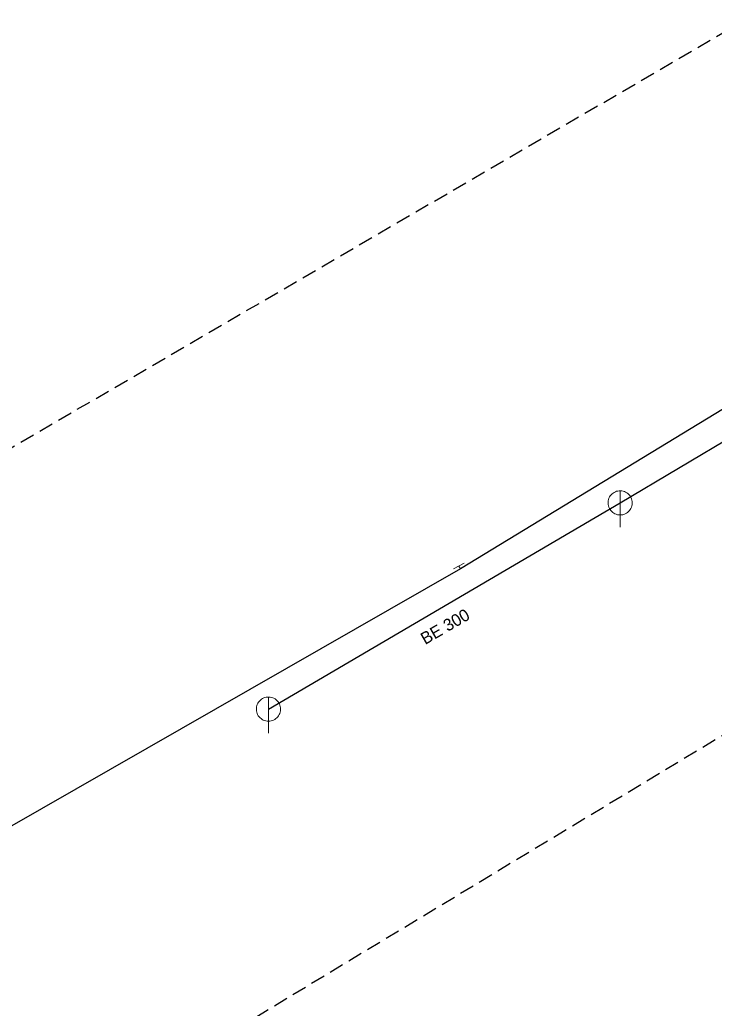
# Model space of a CAD drawing. Extents: x -689189 to -688666, y -973229 to -972850.
# Drawn here: x -689130.1 to -689072.6, y -973144.4 to -973062.7 of the extents above; entities that cross this region are included whole.
import ezdxf

# ---------------------------------------------------------------- set-up
doc = ezdxf.new("R2010")
doc.units = 0
doc.header["$LTSCALE"] = 0.4
doc.linetypes.add('MEDIUM_DASHED', pattern=[4.5, 3, -1.5])
doc.layers.add('1', color=7, linetype='Continuous')
for name, color, linetype, lineweight in [('14', 7, 'Continuous', 13), ('17', 7, 'Continuous', 25), ('22', 7, 'Continuous', 13), ('34', 7, 'Continuous', 13), ('63', 7, 'MEDIUM_DASHED', 25)]:
    doc.layers.add(name, color=color, linetype=linetype, lineweight=lineweight)

msp = doc.modelspace()

# ---------------------------------------------------------------- linework, layer by layer
at = {"layer": '14', "lineweight": 25}
for p, q in [((-689080.41, -973102.649), (-689056.149, -973088.239)), ((-689109.5, -973119.699), (-689080.41, -973102.649))]:
    msp.add_line(p, q, dxfattribs=at)
at = {"layer": '14'}
msp.add_line((-689093.62, -973108.102), (-689093.746, -973107.869), dxfattribs=at)
at = {"layer": '17'}
msp.add_lwpolyline([(-688981.288, -973042.24), (-688991.359, -973047.32), (-689025.954, -973066.95), (-689093.62, -973108.102), (-689137.019, -973132.93)], dxfattribs=at)
at = {"layer": '22'}
for p, q in [((-689080.41, -973104.65), (-689080.409, -973101.65)), ((-689109.5, -973121.7), (-689109.499, -973118.7))]:
    msp.add_line(p, q, dxfattribs=at)
for points in [[(-689079.41, -973102.65), (-689079.415, -973102.541), (-689079.433, -973102.433), (-689079.463, -973102.327), (-689079.503, -973102.226), (-689079.555, -973102.129), (-689079.617, -973102.039), (-689079.689, -973101.956), (-689079.769, -973101.882), (-689079.857, -973101.816), (-689079.951, -973101.761), (-689080.051, -973101.716), (-689080.156, -973101.683), (-689080.263, -973101.661), (-689080.372, -973101.651), (-689080.482, -973101.653), (-689080.59, -973101.667), (-689080.697, -973101.692), (-689080.8, -973101.729), (-689080.898, -973101.778), (-689080.99, -973101.836), (-689081.076, -973101.905), (-689081.153, -973101.982), (-689081.222, -973102.068), (-689081.281, -973102.16), (-689081.329, -973102.258), (-689081.366, -973102.361), (-689081.392, -973102.468), (-689081.406, -973102.576), (-689081.409, -973102.686), (-689081.399, -973102.795), (-689081.378, -973102.902), (-689081.344, -973103.006), (-689081.3, -973103.106), (-689081.245, -973103.201), (-689081.179, -973103.289), (-689081.105, -973103.369), (-689081.022, -973103.441), (-689080.932, -973103.503), (-689080.836, -973103.555), (-689080.734, -973103.596), (-689080.629, -973103.626), (-689080.521, -973103.644), (-689080.411, -973103.65), (-689080.302, -973103.644), (-689080.194, -973103.626), (-689080.089, -973103.597), (-689079.987, -973103.556), (-689079.89, -973103.504), (-689079.8, -973103.442), (-689079.717, -973103.371), (-689079.642, -973103.291), (-689079.577, -973103.203), (-689079.521, -973103.109), (-689079.477, -973103.009), (-689079.443, -973102.905), (-689079.421, -973102.797), (-689079.411, -973102.688)], [(-689108.5, -973119.7), (-689108.505, -973119.591), (-689108.523, -973119.483), (-689108.553, -973119.377), (-689108.593, -973119.276), (-689108.645, -973119.179), (-689108.707, -973119.089), (-689108.779, -973119.006), (-689108.859, -973118.932), (-689108.947, -973118.866), (-689109.041, -973118.811), (-689109.141, -973118.766), (-689109.246, -973118.733), (-689109.353, -973118.711), (-689109.462, -973118.701), (-689109.572, -973118.703), (-689109.68, -973118.717), (-689109.787, -973118.742), (-689109.89, -973118.779), (-689109.988, -973118.828), (-689110.08, -973118.886), (-689110.166, -973118.955), (-689110.243, -973119.032), (-689110.312, -973119.118), (-689110.371, -973119.21), (-689110.419, -973119.308), (-689110.456, -973119.411), (-689110.482, -973119.518), (-689110.496, -973119.626), (-689110.499, -973119.736), (-689110.489, -973119.845), (-689110.468, -973119.952), (-689110.434, -973120.056), (-689110.39, -973120.156), (-689110.335, -973120.251), (-689110.269, -973120.339), (-689110.195, -973120.419), (-689110.112, -973120.491), (-689110.022, -973120.553), (-689109.926, -973120.605), (-689109.824, -973120.646), (-689109.719, -973120.676), (-689109.611, -973120.694), (-689109.501, -973120.7), (-689109.392, -973120.694), (-689109.284, -973120.676), (-689109.179, -973120.647), (-689109.077, -973120.606), (-689108.98, -973120.554), (-689108.89, -973120.492), (-689108.807, -973120.421), (-689108.732, -973120.341), (-689108.667, -973120.253), (-689108.611, -973120.159), (-689108.567, -973120.059), (-689108.533, -973119.955), (-689108.511, -973119.847), (-689108.501, -973119.738)]]:
    msp.add_lwpolyline(points, close=True, dxfattribs=at)
at = {"layer": '34'}
msp.add_line((-689093.306, -973107.629), (-689094.185, -973108.107), dxfattribs=at)
at = {"layer": '63'}
msp.add_lwpolyline([(-689164.065, -973177.51), (-689187.511, -973131.176), (-688767.155, -972886.107), (-688767.155, -972886.107), (-688777.761, -972958.121), (-688777.761, -972958.121), (-688989.335, -973072.002), (-688989.335, -973072.002)], close=True, dxfattribs=at)

# ---------------------------------------------------------------- texts
at = {"layer": '1'}
msp.add_text('BE 300', height=1, rotation=30, dxfattribs=at).set_placement((-689096.538, -973114.404))

doc.saveas('drawing.dxf')
